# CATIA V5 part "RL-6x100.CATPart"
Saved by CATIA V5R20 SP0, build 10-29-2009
Part number: _RL-6x100
Definition: NONE
Nomenclature: _RL-6x100
Source: Unknown
Description: PART-_RL-6x100-DESC
Bounding box of the stored display mesh (mm): x -100 to 7.5, y -3.7 to 3.7, z -3.7 to 3.7
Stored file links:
  C:\Users\Utente\Desktop\IO LAVORO\3D X SITO CF\X SITO\PLASTICA\RL\RL-6x100.CATPart
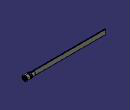
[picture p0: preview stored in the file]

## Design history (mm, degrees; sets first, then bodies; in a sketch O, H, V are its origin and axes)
Body1 "_RL-6x100" (main body)
  Solid1: solid without history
